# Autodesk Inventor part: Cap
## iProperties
Created: 2002-02
Part Number: Cap
Document SubType Name: Modeling
Designer: ***
Control State: 0
Master: False
Checked Out: False
Shininess: 77.0
Angle Display Precision: 2
Document Length Units: 11269
Document Angle Units: 11279
Document Time Units: 11290
Document Mass Units: 11283
Document Length Units Precision: 3
Document Angle Units Precision: 2
Density: 0.0
Volumn: 0.0
Area: 0.0
PropertySet Name: Model Information
Author: ***
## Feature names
1. Extrusion1
2. Extrusion2
3. Hole1
4. Hole2
5. Mirror1
6. Hole3
